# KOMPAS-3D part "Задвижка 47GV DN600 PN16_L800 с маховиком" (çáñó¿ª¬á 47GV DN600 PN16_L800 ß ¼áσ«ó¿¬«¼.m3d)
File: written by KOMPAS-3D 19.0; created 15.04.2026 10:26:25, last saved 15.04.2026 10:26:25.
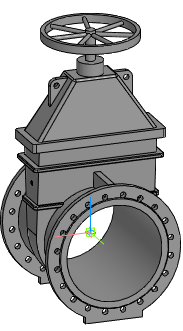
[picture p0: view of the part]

Document properties: Автор: Евгений; Полное имя файла: Z:\3.Личные\kachalov\3d для проектировщиков\2.1 Тип 47GV, 47GV.Z\Задвижка 47GV_DN40-DN600\stp_Задвижка 47GV\Задвижка 47GV DN600 PN16_L800 с маховиком.m3d

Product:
- Part/product: Задвижка 47GV DN600 PN16_L800 с маховиком

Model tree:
1. Операция без истории:1  (labels: Задвижка 47GV DN600 PN16_L800 с маховиком)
